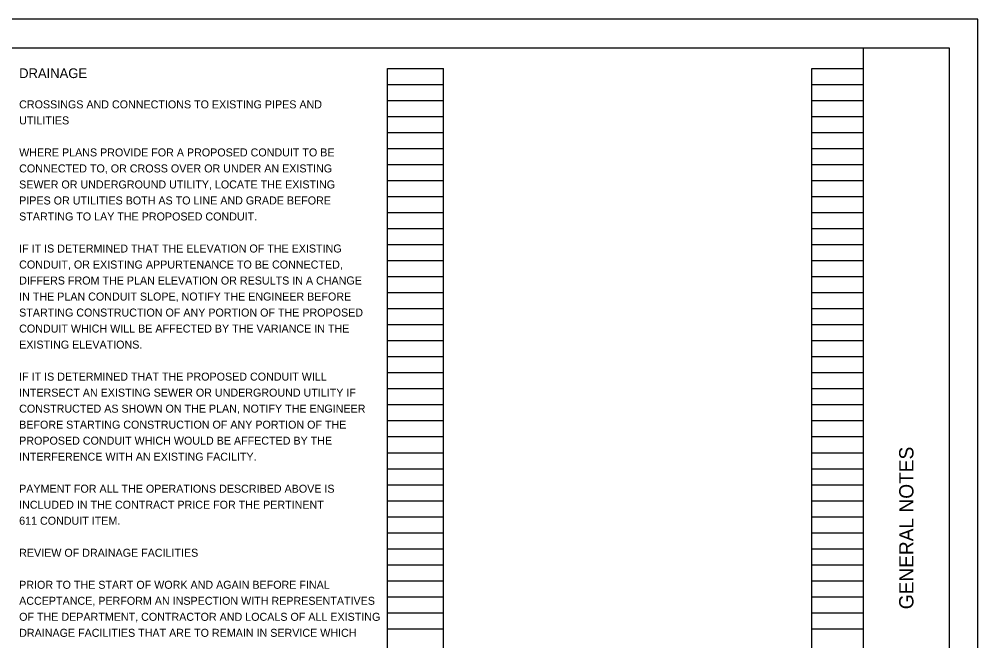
# Model space of a CAD drawing. Extents: x 0 to 34, y -49.5 to 22.
# Drawn here: x 17.24 to 34, y 11.13 to 22 of the extents above; entities that cross this region are included whole.
import ezdxf

# ---------------------------------------------------------------- set-up
doc = ezdxf.new("R2010")
doc.units = 0
for name, color, linetype in [('SH_Border', 7, 'Continuous'), ('SH_Cut_Line', 7, 'Continuous'), ('SH_Data', 7, 'Continuous'), ('SH_Text', 7, 'Continuous')]:
    doc.layers.add(name, color=color, linetype=linetype)

msp = doc.modelspace()

# ---------------------------------------------------------------- linework, layer by layer
at = {"layer": 'SH_Border'}
msp.add_line((32, 0.5), (32, 21.5), dxfattribs=at)
msp.add_lwpolyline([(1.5, 21.5), (33.5, 21.5), (33.5, 0.5), (1.5, 0.5)], close=True, dxfattribs=at)
at = {"layer": 'SH_Cut_Line'}
msp.add_lwpolyline([(0, 0), (34, 0), (34, 22), (0, 22)], close=True, dxfattribs=at)
at = {"layer": 'SH_Data'}
for p, q in [((23.68, 0.98), (23.68, 21.14)), ((23.68, 21.14), (24.66, 21.14)), ((24.66, 0.98), (24.66, 21.14)), ((31.1, 0.98), (31.1, 21.14)), ((31.1, 21.14), (32, 21.14)), ((32, 0.98), (32, 21.14)), ((23.68, 20.86), (24.66, 20.86)), ((31.1, 20.86), (32, 20.86)), ((23.68, 20.58), (24.66, 20.58)), ((31.1, 20.58), (32, 20.58)), ((23.68, 20.3), (24.66, 20.3)), ((31.1, 20.3), (32, 20.3)), ((23.68, 20.02), (24.66, 20.02)), ((31.1, 20.02), (32, 20.02)), ((23.68, 19.74), (24.66, 19.74)), ((31.1, 19.74), (32, 19.74)), ((23.68, 19.46), (24.66, 19.46)), ((31.1, 19.46), (32, 19.46)), ((23.68, 19.18), (24.66, 19.18)), ((31.1, 19.18), (32, 19.18)), ((23.68, 18.9), (24.66, 18.9)), ((31.1, 18.9), (32, 18.9)), ((23.68, 18.62), (24.66, 18.62)), ((31.1, 18.62), (32, 18.62)), ((23.68, 18.34), (24.66, 18.34)), ((31.1, 18.34), (32, 18.34)), ((23.68, 18.06), (24.66, 18.06)), ((31.1, 18.06), (32, 18.06)), ((23.68, 17.78), (24.66, 17.78)), ((31.1, 17.78), (32, 17.78)), ((23.68, 17.5), (24.66, 17.5)), ((31.1, 17.5), (32, 17.5)), ((23.68, 17.22), (24.66, 17.22)), ((31.1, 17.22), (32, 17.22)), ((23.68, 16.94), (24.66, 16.94)), ((31.1, 16.94), (32, 16.94)), ((23.68, 16.66), (24.66, 16.66)), ((31.1, 16.66), (32, 16.66)), ((23.68, 16.38), (24.66, 16.38)), ((31.1, 16.38), (32, 16.38)), ((23.68, 16.1), (24.66, 16.1)), ((31.1, 16.1), (32, 16.1)), ((23.68, 15.82), (24.66, 15.82)), ((31.1, 15.82), (32, 15.82)), ((23.68, 15.54), (24.66, 15.54)), ((31.1, 15.54), (32, 15.54)), ((23.68, 15.26), (24.66, 15.26)), ((31.1, 15.26), (32, 15.26)), ((23.68, 14.98), (24.66, 14.98)), ((31.1, 14.98), (32, 14.98)), ((23.68, 14.7), (24.66, 14.7)), ((31.1, 14.7), (32, 14.7)), ((23.68, 14.42), (24.66, 14.42)), ((31.1, 14.42), (32, 14.42)), ((23.68, 14.14), (24.66, 14.14)), ((31.1, 14.14), (32, 14.14)), ((23.68, 13.86), (24.66, 13.86)), ((31.1, 13.86), (32, 13.86)), ((23.68, 13.58), (24.66, 13.58)), ((31.1, 13.58), (32, 13.58)), ((23.68, 13.3), (24.66, 13.3)), ((31.1, 13.3), (32, 13.3)), ((23.68, 13.02), (24.66, 13.02)), ((31.1, 13.02), (32, 13.02)), ((23.68, 12.74), (24.66, 12.74)), ((31.1, 12.74), (32, 12.74)), ((23.68, 12.46), (24.66, 12.46)), ((31.1, 12.46), (32, 12.46)), ((23.68, 12.18), (24.66, 12.18)), ((31.1, 12.18), (32, 12.18)), ((23.68, 11.9), (24.66, 11.9)), ((31.1, 11.9), (32, 11.9)), ((23.68, 11.62), (24.66, 11.62)), ((31.1, 11.62), (32, 11.62)), ((23.68, 11.34), (24.66, 11.34)), ((31.1, 11.34), (32, 11.34))]:
    msp.add_line(p, q, dxfattribs=at)

# ---------------------------------------------------------------- texts
msp.add_text('GENERAL NOTES', height=0.25, rotation=90, dxfattribs=at).set_placement((32.875, 11.682))
at = {"layer": 'SH_Text'}
for s, height, p in [('DRAINAGE', 0.17, (17.24, 20.97)), ('CROSSINGS AND CONNECTIONS TO EXISTING PIPES AND', 0.14, (17.24, 20.44)), ('UTILITIES', 0.14, (17.24, 20.16)), ('WHERE PLANS PROVIDE FOR A PROPOSED CONDUIT TO BE', 0.14, (17.24, 19.6)), ('CONNECTED TO, OR CROSS OVER OR UNDER AN EXISTING', 0.14, (17.24, 19.32)), ('SEWER OR UNDERGROUND UTILITY, LOCATE THE EXISTING', 0.14, (17.24, 19.04)), ('PIPES OR UTILITIES BOTH AS TO LINE AND GRADE BEFORE', 0.14, (17.24, 18.76)), ('STARTING TO LAY THE PROPOSED CONDUIT.', 0.14, (17.24, 18.48)), ('IF IT IS DETERMINED THAT THE ELEVATION OF THE EXISTING', 0.14, (17.24, 17.92)), ('CONDUIT, OR EXISTING APPURTENANCE TO BE CONNECTED,', 0.14, (17.24, 17.64)), ('DIFFERS FROM THE PLAN ELEVATION OR RESULTS IN A CHANGE', 0.14, (17.24, 17.36)), ('IN THE PLAN CONDUIT SLOPE, NOTIFY THE ENGINEER BEFORE', 0.14, (17.24, 17.08)), ('STARTING CONSTRUCTION OF ANY PORTION OF THE PROPOSED', 0.14, (17.24, 16.8)), ('CONDUIT WHICH WILL BE AFFECTED BY THE VARIANCE IN THE', 0.14, (17.24, 16.52)), ('EXISTING ELEVATIONS.', 0.14, (17.24, 16.24)), ('IF IT IS DETERMINED THAT THE PROPOSED CONDUIT WILL', 0.14, (17.24, 15.68)), ('INTERSECT AN EXISTING SEWER OR UNDERGROUND UTILITY IF', 0.14, (17.24, 15.4)), ('CONSTRUCTED AS SHOWN ON THE PLAN, NOTIFY THE ENGINEER', 0.14, (17.24, 15.12)), ('BEFORE STARTING CONSTRUCTION OF ANY PORTION OF THE', 0.14, (17.24, 14.84)), ('PROPOSED CONDUIT WHICH WOULD BE AFFECTED BY THE', 0.14, (17.24, 14.56)), ('INTERFERENCE WITH AN EXISTING FACILITY.', 0.14, (17.24, 14.28)), ('PAYMENT FOR ALL THE OPERATIONS DESCRIBED ABOVE IS', 0.14, (17.24, 13.72)), ('INCLUDED IN THE CONTRACT PRICE FOR THE PERTINENT', 0.14, (17.24, 13.44)), ('611 CONDUIT ITEM.', 0.14, (17.24, 13.16)), ('REVIEW OF DRAINAGE FACILITIES', 0.14, (17.24, 12.6)), ('PRIOR TO THE START OF WORK AND AGAIN BEFORE FINAL', 0.14, (17.24, 12.04)), ('ACCEPTANCE, PERFORM AN INSPECTION WITH REPRESENTATIVES', 0.14, (17.24, 11.76)), ('OF THE DEPARTMENT, CONTRACTOR AND LOCALS OF ALL EXISTING', 0.14, (17.24, 11.48)), ('DRAINAGE FACILITIES THAT ARE TO REMAIN IN SERVICE WHICH', 0.14, (17.24, 11.2))]:
    msp.add_text(s, height=height, dxfattribs=at).set_placement(p)

doc.saveas('drawing.dxf')
